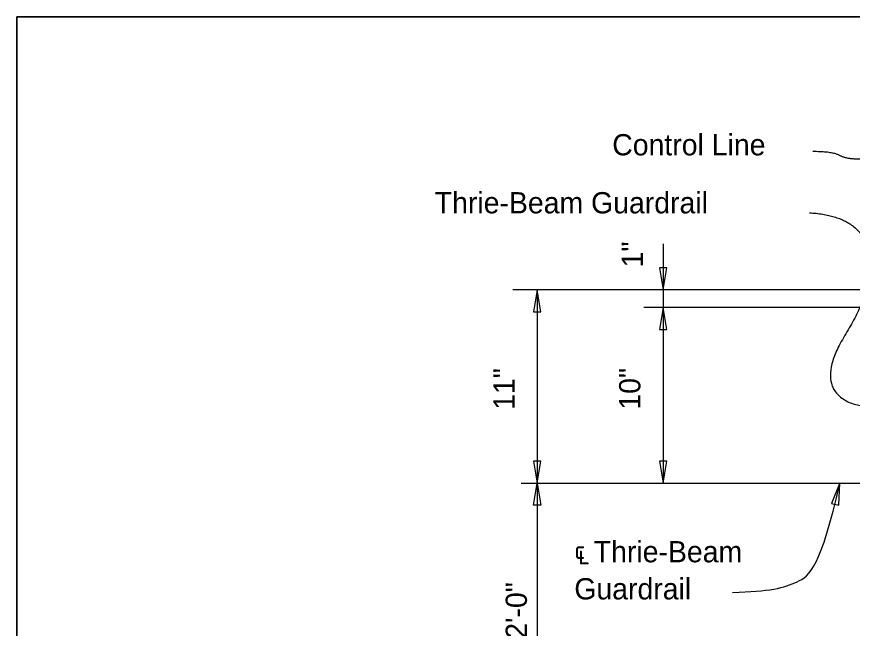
# Model space of a CAD drawing. Extents: x 0 to 41.1, y 0 to 25.9.
# Drawn here: x 0 to 7.93, y 20.15 to 25.95 of the extents above; entities that cross this region are included whole.
import ezdxf

# ---------------------------------------------------------------- set-up
doc = ezdxf.new("R2010")
doc.units = 0
for name, color, linetype in [('Dimension', 7, 'Continuous'), ('Miscellaneous', 7, 'Continuous'), ('Miscellaneous1', 7, 'Continuous'), ('TextStructures', 7, 'Continuous')]:
    doc.layers.add(name, color=color, linetype=linetype)

msp = doc.modelspace()

# ---------------------------------------------------------------- linework, layer by layer
at = {"layer": 'Dimension'}
for p, q in [((6.1326, 23.7924), (6.1326, 21.5218)), ((8.5917, 23.3552), (4.7068, 23.3552)), ((4.936, 23.3552), (4.936, 16.3552)), ((8.4116, 23.1885), (5.9481, 23.1885))]:
    msp.add_line(p, q, dxfattribs=at)
for points in [[(6.1326, 23.3552), (6.1678, 23.5634), (6.0973, 23.5634)], [(4.936, 23.3552), (4.9007, 23.1469), (4.9712, 23.1469)], [(6.1326, 23.1885), (6.0973, 22.9802), (6.1678, 22.9802)], [(4.936, 21.5218), (4.9712, 21.7301), (4.9007, 21.7301)], [(6.1326, 21.5218), (6.1678, 21.7301), (6.0973, 21.7301)], [(4.936, 21.5218), (4.9712, 21.3136), (4.9007, 21.3136)], [(7.8091, 21.5253), (7.7282, 21.3302), (7.7969, 21.3145)]]:
    msp.add_lwpolyline(points, close=True, dxfattribs=at)
for points, degree in [([(7.5511, 24.6699), (7.7348, 24.6699), (7.8655, 24.5992), (8.0493, 24.5992), (8.2365, 24.5992)], 2), ([(7.5193, 24.0867), (7.9963, 24.0584), (8.1591, 23.4147), (7.5755, 22.4743), (8.1352, 22.145), (8.5122, 22.4957)], 2), ([(6.7886, 20.4861), (7.1368, 20.492), (7.4262, 20.566), (7.6243, 20.7192), (7.8091, 21.5253)], 3)]:
    msp.add_open_spline(points, degree=degree, dxfattribs=at)
at = {"layer": 'Miscellaneous'}
msp.add_line((4.7854, 21.5218), (8.4116, 21.5218), dxfattribs=at)
at = {"layer": 'Miscellaneous1'}
msp.add_lwpolyline([(0, 25.9461), (41.0506, 25.9461), (41.0506, 0), (0, 0)], close=True, dxfattribs=at)
at = {"layer": 'TextStructures'}
msp.add_lwpolyline([(0, 0), (41.0506, 0), (41.0506, 25.9461), (0, 25.9461)], close=True, dxfattribs=at)

# ---------------------------------------------------------------- texts
at = {"layer": 'Dimension'}
for s, p in [('℄ Thrie-Beam', (5.2891, 20.771)), ('Guardrail', (5.2891, 20.419))]:
    msp.add_text(s, height=0.2016, dxfattribs=at).set_placement(p)
at = {"layer": 'TextStructures'}
for s, p in [('Control Line', (5.649, 24.6308)), ('Thrie-Beam Guardrail', (3.9651, 24.0807))]:
    msp.add_text(s, height=0.2016, dxfattribs=at).set_placement(p)
for s, p in [('1"', (5.9401, 23.5683)), ('11"', (4.7237, 22.2171)), ('10"', (5.9157, 22.219)), ('Varies 1\'-9" to 2\'-0"', (4.8397, 18.2953))]:
    msp.add_text(s, height=0.2016, rotation=90, dxfattribs=at).set_placement(p)

doc.saveas('drawing.dxf')
